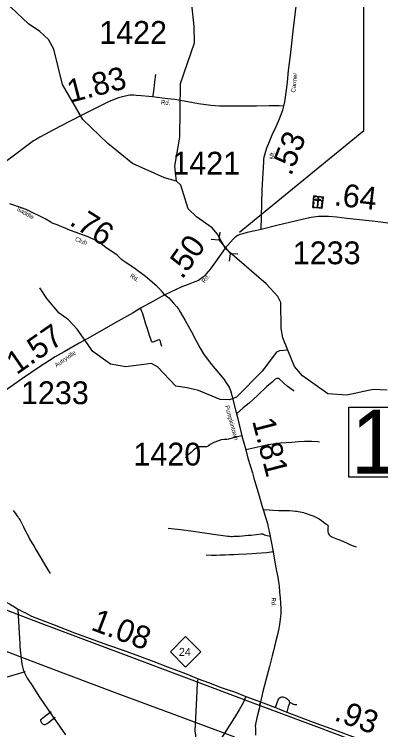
# Model space of a CAD drawing. Extents: x 2093524 to 2270757, y 289120 to 570408.
# Drawn here: x 2112932 to 2120967, y 449270 to 464958 of the extents above; entities that cross this region are included whole.
import ezdxf

# ---------------------------------------------------------------- set-up
doc = ezdxf.new("R2010")
doc.units = 0
for name, color, linetype in [('Exist Cultural Cemetery CELL', 7, 'Continuous'), ('Exist Hydrographic Creek Single Shore', 7, 'Continuous'), ('Exist Hydrographic Misc Water Feature', 7, 'Continuous'), ('Exist Railroad Mainline', 7, 'Continuous'), ('Exist Road Non-System Type 51', 7, 'Continuous'), ('Exist Road Primary NC Attributed', 7, 'Continuous'), ('Exist Road Primary NC Mileage Hundredths English Label', 7, 'Continuous'), ('Exist Road Primary NC Shield CELL', 7, 'Continuous'), ('Exist Road Primary NC Shield Number Label', 7, 'Continuous'), ('Exist Road Secondary Mileage Hundredths English Label', 7, 'Continuous'), ('Exist Road Secondary Structure Pipe CELL', 7, 'Continuous'), ('Exist Road Secondary Structure Pipe Number Label', 7, 'Continuous'), ('Exist Road Secondary Structure Standard Bridge Number Label', 7, 'Continuous'), ('Exist Road Secondary Type 51 Attributed', 7, 'Continuous'), ('Exist Road Secondary Type 51 Label', 7, 'Continuous'), ('Exist Road Secondary Type 51 Number Label', 7, 'Continuous'), ('Exist Utilities Telephone Line', 7, 'Continuous')]:
    doc.layers.add(name, color=color, linetype=linetype)

msp = doc.modelspace()

# ---------------------------------------------------------------- linework, layer by layer
at = {"layer": 'Exist Cultural Cemetery CELL'}
for points in [[(2119504, 460976), (2119702, 460956), (2119677, 460703), (2119479, 460722)], [(2119493, 460859), (2119497, 460902), (2119508, 460901), (2119504, 460858)], [(2119500, 460933), (2119511, 460932), (2119514, 460964), (2119555, 460960), (2119556, 460971), (2119504, 460976)], [(2119538, 460904), (2119536, 460885), (2119653, 460874), (2119655, 460892)], [(2119610, 460936), (2119591, 460938), (2119571, 460736), (2119590, 460734)], [(2119578, 460968), (2119629, 460963), (2119628, 460952), (2119577, 460957)], [(2119698, 460913), (2119687, 460914), (2119690, 460946), (2119650, 460950), (2119651, 460961), (2119702, 460956)], [(2119512, 460719), (2119513, 460731), (2119491, 460733), (2119495, 460773), (2119484, 460774), (2119479, 460722)], [(2119486, 460792), (2119490, 460835), (2119501, 460834), (2119497, 460791)], [(2119644, 460706), (2119645, 460717), (2119667, 460715), (2119671, 460755), (2119682, 460754), (2119677, 460703)], [(2119673, 460776), (2119677, 460819), (2119689, 460818), (2119684, 460775)], [(2119679, 460841), (2119684, 460884), (2119695, 460883), (2119691, 460840)], [(2119537, 460728), (2119622, 460720), (2119621, 460708), (2119536, 460717)]]:
    msp.add_lwpolyline(points, close=True, dxfattribs=at)
at = {"layer": 'Exist Hydrographic Creek Single Shore'}
for points in [[(2116489, 461297), (2116455, 461629), (2116560, 462264), (2116580, 463438), (2116884, 464331), (2116874, 464688), (2116822, 465172), (2117018, 465991), (2117009, 466280), (2116831, 466972), (2116679, 467346), (2116310, 467928), (2115948, 468752), (2115872, 468966), (2115510, 469813), (2115317, 470188), (2115173, 470713), (2115212, 471296), (2115343, 471854), (2115333, 472287), (2115223, 472664)], [(2116489, 461297), (2116222, 461372), (2115521, 461684), (2114986, 462125), (2114434, 462654), (2113989, 463417), (2113802, 464192), (2113685, 464408), (2113492, 464582), (2113242, 464748), (2112857, 465113), (2112396, 465726)], [(2117553, 459826), (2117386, 460135), (2117268, 460275), (2116927, 460514), (2116742, 460689), (2116581, 461214), (2116489, 461297)], [(2118931, 457591), (2118821, 457865), (2118787, 458066), (2118775, 458640), (2118708, 458773), (2118457, 459047), (2117649, 459742), (2117553, 459826)], [(2121109, 456717), (2120801, 456727), (2120226, 456607), (2119810, 456638), (2119250, 457027), (2119074, 457234), (2118931, 457591)]]:
    msp.add_lwpolyline(points, dxfattribs=at)
at = {"layer": 'Exist Hydrographic Misc Water Feature'}
msp.add_lwpolyline([(2118931, 457591), (2118748, 457575), (2118681, 457550), (2118366, 457133), (2117801, 456564), (2117652, 456504), (2117443, 456512), (2116968, 456708), (2116726, 456766), (2116475, 456807), (2116075, 457228), (2115940, 457303), (2115375, 457226), (2115041, 457285), (2114656, 457565), (2114312, 458054), (2114120, 458261), (2113919, 458403), (2113643, 458727), (2113492, 458959)], dxfattribs=at)
at = {"layer": 'Exist Railroad Mainline'}
for points in [[(2107219, 453960), (2107704, 453778), (2108825, 453368), (2109960, 452952), (2111077, 452536), (2112390, 452041), (2113015, 451799)], [(2113015, 451799), (2113513, 451606), (2115446, 450884), (2116647, 450432), (2118165, 449863), (2119561, 449338), (2120720, 448904), (2121926, 448462), (2122765, 448156), (2122833, 448131)]]:
    msp.add_lwpolyline(points, dxfattribs=at)
at = {"layer": 'Exist Road Non-System Type 51'}
msp.add_line((2118330, 449883), (2118301, 449791), dxfattribs=at)
for points in [[(2116028, 463638), (2116008, 463474), (2115989, 463328), (2115977, 463224), (2115964, 463146)], [(2116164, 457671), (2116156, 457715), (2116136, 457783), (2116135, 457793), (2116133, 457801), (2116125, 457812), (2116117, 457818), (2116111, 457817), (2116078, 457810), (2115992, 457774), (2115971, 457770), (2115954, 457768), (2115946, 457774), (2115941, 457792), (2115895, 457918), (2115850, 458062), (2115812, 458187), (2115774, 458317), (2115741, 458409), (2115729, 458443), (2115697, 458511)], [(2119067, 456694), (2119045, 456712), (2118918, 456805), (2118826, 456885), (2118747, 456956), (2118723, 456970), (2118687, 456970), (2118654, 456954), (2118584, 456892), (2118472, 456795), (2118269, 456607), (2118081, 456434), (2117952, 456325), (2117808, 456199)], [(2117922, 455717), (2117858, 455697), (2117740, 455669), (2117626, 455642), (2117594, 455632), (2117544, 455632), (2117470, 455624), (2117408, 455607), (2117308, 455571), (2117228, 455523), (2117182, 455487), (2117150, 455476), (2117084, 455472), (2116972, 455470), (2116923, 455446), (2116867, 455409), (2116813, 455351), (2116735, 455289), (2116707, 455261), (2116699, 455245), (2116683, 455222)], [(2119621, 455576), (2119589, 455580), (2119457, 455589), (2119297, 455588), (2119167, 455582), (2119017, 455571), (2118773, 455550), (2118497, 455519), (2118337, 455483), (2118011, 455404)], [(2113724, 452693), (2113667, 452789), (2113582, 452935), (2113507, 453060), (2113443, 453171), (2113398, 453245), (2113352, 453325), (2113323, 453369), (2113303, 453403), (2113285, 453428), (2113265, 453460), (2113247, 453498), (2113218, 453554), (2113194, 453608), (2113165, 453661), (2113143, 453709), (2113121, 453757), (2113099, 453799), (2113076, 453841), (2113058, 453871), (2113046, 453891), (2113027, 453919), (2113008, 453946), (2112985, 453978), (2112965, 454010), (2112939, 454048), (2112917, 454078)], [(2118389, 454098), (2118519, 454090), (2118599, 454087), (2118723, 454080), (2118845, 454077), (2118968, 454077), (2119040, 454071), (2119101, 454064), (2119127, 454060), (2119160, 454055), (2119199, 454047), (2119237, 454040), (2119274, 454031), (2119307, 454021), (2119343, 454010), (2119414, 453984), (2119484, 453959), (2119526, 453939), (2119572, 453917), (2119614, 453894), (2119666, 453856), (2119707, 453828), (2119745, 453801), (2119777, 453779), (2119796, 453765), (2119805, 453758), (2119811, 453743), (2119813, 453729), (2119811, 453695), (2119810, 453635), (2119811, 453608), (2119816, 453583), (2119824, 453563), (2119835, 453546), (2119849, 453531), (2119867, 453517), (2119883, 453508), (2119911, 453494), (2119943, 453480), (2120021, 453450), (2120087, 453427), (2120169, 453392), (2120233, 453362), (2120307, 453327), (2120364, 453305), (2120429, 453281)], [(2118543, 453509), (2118447, 453530), (2118421, 453538), (2118399, 453548), (2118381, 453556), (2118369, 453558), (2118361, 453558), (2118349, 453558), (2118233, 453545), (2118127, 453532), (2118061, 453526), (2117994, 453521), (2117933, 453516), (2117866, 453510), (2117810, 453506), (2117774, 453504), (2117744, 453504), (2117717, 453503), (2117688, 453503), (2117654, 453505), (2117614, 453509), (2117564, 453516), (2117348, 453543), (2117106, 453577), (2116806, 453627), (2116579, 453650), (2116371, 453677), (2116306, 453684)], [(2118605, 453170), (2118472, 453149), (2118354, 453140), (2118242, 453133), (2118150, 453127), (2118026, 453120), (2117848, 453113), (2117739, 453108), (2117653, 453105), (2117553, 453101), (2117449, 453096), (2117367, 453093), (2117301, 453089), (2117257, 453088), (2117142, 453097)], [(2113169, 450537), (2112743, 450414), (2112397, 450312), (2112300, 450290), (2112255, 450279), (2112183, 450254), (2112102, 450226), (2112054, 450207), (2112046, 450203), (2112026, 450198), (2111988, 450196), (2111916, 450192), (2111828, 450190), (2111805, 450188), (2111771, 450187), (2111717, 450182), (2111623, 450166)], [(2116922, 449040), (2116909, 449147), (2116896, 449247), (2116913, 449527), (2116935, 449959), (2116949, 450289), (2116966, 450389)], [(2118009, 450000), (2117954, 449857), (2117864, 449708), (2117761, 449537), (2117610, 449298), (2117545, 449203), (2117410, 448992), (2117362, 448904), (2117339, 448847)], [(2118661, 449754), (2118688, 449844), (2118704, 449884), (2118720, 449922), (2118731, 449948), (2118743, 449964), (2118759, 449978), (2118779, 449986), (2118797, 449991), (2118817, 449991), (2118841, 449985), (2118863, 449975), (2118891, 449961), (2118913, 449945), (2118933, 449931), (2118947, 449920), (2118957, 449903), (2118962, 449889)], [(2118330, 449883), (2118305, 449730), (2118251, 449532), (2118218, 449394), (2118215, 449343), (2118218, 449310), (2118222, 449217), (2118222, 449149)], [(2118962, 449889), (2118966, 449856), (2118960, 449828), (2118940, 449769), (2118910, 449657)], [(2118962, 449889), (2118996, 449862), (2119016, 449849), (2119034, 449839), (2119058, 449830), (2119080, 449826), (2119098, 449825), (2119126, 449825)], [(2113826, 449536), (2113671, 449412), (2113653, 449398), (2113634, 449388), (2113618, 449382), (2113601, 449377), (2113584, 449378), (2113569, 449383), (2113558, 449392), (2113546, 449405), (2113537, 449415), (2113529, 449427), (2113522, 449440), (2113515, 449455), (2113512, 449467), (2113513, 449481), (2113516, 449492), (2113525, 449503), (2113536, 449515), (2113554, 449533), (2113594, 449563), (2113738, 449669)]]:
    msp.add_lwpolyline(points, dxfattribs=at)
at = {"layer": 'Exist Road Primary NC Attributed'}
for points in [[(2108369, 453970), (2108678, 453841), (2108992, 453716), (2109651, 453469), (2109957, 453357), (2110420, 453180), (2110927, 452990), (2111158, 452895), (2111300, 452839), (2111481, 452761), (2111679, 452677), (2111876, 452577), (2111992, 452513), (2112719, 452091), (2112846, 452016), (2112934, 451961), (2113011, 451916)], [(2113011, 451916), (2113059, 451889), (2113109, 451863), (2113176, 451830), (2113312, 451761), (2113461, 451703), (2113769, 451585), (2114254, 451396), (2115001, 451124), (2115317, 451017), (2115676, 450881), (2115992, 450764), (2116293, 450651), (2116684, 450499), (2116966, 450389), (2117194, 450303), (2117467, 450198), (2117601, 450153), (2117760, 450099), (2117886, 450052), (2118009, 450000), (2118113, 449965), (2118330, 449883)], [(2118330, 449883), (2118661, 449754), (2118910, 449657), (2119484, 449439), (2119950, 449264), (2120430, 449092), (2120558, 449049), (2120718, 448994), (2120871, 448938), (2121055, 448870), (2121206, 448816), (2121382, 448751), (2121570, 448681), (2121778, 448608), (2122085, 448495), (2122254, 448410), (2122440, 448345), (2122678, 448257), (2122919, 448177)]]:
    msp.add_lwpolyline(points, dxfattribs=at)
at = {"layer": 'Exist Road Primary NC Shield CELL'}
msp.add_lwpolyline([(2116355, 450978), (2116688, 451311), (2117021, 450978), (2116688, 450645)], close=True, dxfattribs=at)
at = {"layer": 'Exist Road Secondary Structure Pipe CELL'}
for p, q in [((2117438, 460179), (2117417, 460014)), ((2117251, 460025), (2117417, 460014)), ((2117417, 460014), (2117670, 459708)), ((2117649, 459543), (2117670, 459708)), ((2117836, 459697), (2117670, 459708))]:
    msp.add_line(p, q, dxfattribs=at)
at = {"layer": 'Exist Road Secondary Structure Pipe Number Label'}
msp.add_lwpolyline([(2117868, 460183), (2120600, 462409), (2120600, 465976)], dxfattribs=at)
at = {"layer": 'Exist Road Secondary Structure Standard Bridge Number Label'}
msp.add_lwpolyline([(2120265, 456342), (2123981, 456342), (2123981, 454806), (2120265, 454806)], close=True, dxfattribs=at)
at = {"layer": 'Exist Road Secondary Type 51 Attributed'}
for points in [[(2118839, 462945), (2118861, 463041), (2118879, 463139), (2118892, 463241), (2118920, 463471), (2118947, 463727), (2118987, 464057), (2119049, 464589), (2119133, 465328), (2119170, 465620), (2119185, 465724), (2119193, 465758), (2119207, 465808), (2119217, 465848), (2119258, 465944), (2119350, 466149), (2119443, 466359), (2119586, 466677), (2119701, 466924), (2119753, 467026)], [(2118839, 462945), (2118741, 462952), (2118521, 462951), (2118245, 462947), (2117971, 462945), (2117747, 462943), (2117575, 462942), (2117435, 462947), (2117245, 462961), (2116973, 462998), (2116734, 463039), (2116450, 463092), (2116290, 463107), (2115964, 463146), (2115882, 463152), (2115711, 463171), (2115605, 463180), (2115551, 463184), (2115465, 463182), (2115364, 463166), (2115219, 463129), (2115012, 463048), (2114822, 462950), (2114413, 462744), (2113943, 462502), (2113488, 462263), (2113394, 462208), (2113352, 462182), (2113293, 462138), (2113175, 462049), (2112965, 461893), (2112712, 461702)], [(2118345, 460241), (2118368, 461099), (2118379, 461357), (2118394, 461599), (2118402, 461721), (2118406, 461769), (2118413, 461831), (2118425, 461879), (2118447, 461959), (2118471, 462031), (2118510, 462130), (2118590, 462316), (2118671, 462494), (2118746, 462668), (2118794, 462784), (2118818, 462855), (2118839, 462945)], [(2116231, 458805), (2116178, 458865), (2116123, 458927), (2116059, 458994), (2115806, 459209), (2115579, 459378), (2115357, 459530), (2115293, 459577), (2115240, 459623), (2115190, 459673), (2115136, 459713), (2114948, 459840), (2114835, 459922), (2114721, 459995), (2114549, 460075), (2114164, 460219), (2113875, 460342), (2113807, 460364), (2113745, 460385), (2113730, 460401), (2113609, 460472), (2113219, 460661), (2113191, 460677), (2113093, 460715), (2112832, 460805)], [(2121695, 460317), (2121577, 460329), (2121326, 460359), (2121122, 460380), (2120972, 460398), (2120777, 460422), (2120639, 460438), (2120435, 460459), (2120224, 460483), (2120008, 460508), (2119819, 460527), (2119717, 460527), (2119605, 460523), (2119442, 460503), (2119272, 460462), (2119089, 460419), (2118720, 460335), (2118345, 460241)], [(2118345, 460241), (2118217, 460212), (2118039, 460170), (2117943, 460147), (2117913, 460138), (2117879, 460127), (2117833, 460104), (2117798, 460083), (2117762, 460056), (2117728, 460025), (2117553, 459826)], [(2117553, 459826), (2117342, 459527), (2117228, 459369), (2117190, 459325), (2117142, 459268), (2117114, 459234), (2117083, 459204), (2117032, 459161), (2116969, 459122), (2116890, 459089), (2116741, 459035), (2116603, 458982), (2116231, 458805)], [(2116231, 458805), (2116136, 458757), (2115986, 458670), (2115697, 458511), (2115539, 458414), (2115212, 458227), (2115040, 458134), (2114848, 458022), (2114529, 457842), (2114357, 457746), (2114026, 457555), (2113830, 457444), (2113475, 457223), (2113111, 456971), (2112716, 456696)], [(2116231, 458805), (2116324, 458739), (2116425, 458624), (2116493, 458546), (2116537, 458484), (2116579, 458418), (2116676, 458247), (2116807, 458011), (2116922, 457796), (2117006, 457640), (2117083, 457516), (2117139, 457432), (2117254, 457279), (2117419, 457085), (2117481, 457010), (2117531, 456946), (2117581, 456878), (2117616, 456822), (2117642, 456778), (2117670, 456712), (2117703, 456597), (2117808, 456199), (2117826, 456113), (2117922, 455717), (2118011, 455404), (2118056, 455228), (2118155, 454903), (2118188, 454783), (2118227, 454642), (2118300, 454398), (2118362, 454187), (2118389, 454098), (2118441, 453931), (2118482, 453790), (2118500, 453713), (2118514, 453654), (2118524, 453611), (2118534, 453558), (2118543, 453509), (2118573, 453362), (2118595, 453247), (2118605, 453170), (2118647, 452943), (2118685, 452745), (2118709, 452617), (2118724, 452516), (2118737, 452426), (2118750, 452286), (2118763, 452162), (2118773, 452046), (2118776, 451933), (2118775, 451811), (2118764, 451696), (2118750, 451574), (2118735, 451493), (2118721, 451424), (2118698, 451328), (2118669, 451216), (2118639, 451095), (2118614, 450997), (2118587, 450887), (2118564, 450799), (2118526, 450653), (2118480, 450467), (2118414, 450220), (2118384, 450107), (2118359, 450005), (2118330, 449883)], [(2113011, 451916), (2113021, 451645), (2113043, 451269), (2113051, 451169), (2113056, 451086), (2113069, 450955), (2113078, 450897), (2113097, 450704), (2113125, 450590), (2113149, 450531), (2113215, 450402), (2113321, 450243), (2113487, 449982), (2113756, 449590), (2114051, 449155)]]:
    msp.add_lwpolyline(points, dxfattribs=at)
at = {"layer": 'Exist Utilities Telephone Line'}
msp.add_lwpolyline([(2105807, 453400), (2106839, 453144), (2107342, 453027), (2109094, 452364), (2110400, 451877), (2111697, 451383), (2112393, 451121), (2113608, 450660), (2115178, 450072), (2116384, 449622), (2117759, 449111)], dxfattribs=at)

# ---------------------------------------------------------------- texts
at = {"layer": 'Exist Road Primary NC Mileage Hundredths English Label'}
for s, rotation, p in [('1.08', 339.2343, (2114589, 451469)), ('.93', 339.8056, (2119925, 449486))]:
    msp.add_text(s, height=500, rotation=rotation, dxfattribs=at).set_placement(p)
at = {"layer": 'Exist Road Primary NC Shield Number Label'}
msp.add_text('24', height=175, dxfattribs=at).set_placement((2116542, 450889))
at = {"layer": 'Exist Road Secondary Mileage Hundredths English Label'}
for s, rotation, p in [('1.83', 14.4142, (2114165, 463018)), ('.53', 68.9537, (2119002, 461396)), ('.64', 353.5441, (2119929, 460769)), ('.76', 327.4768, (2114117, 460356)), ('.50', 54.8443, (2116614, 459128)), ('1.57', 34.8302, (2112981, 457042)), ('1.81', 284.4409, (2118145, 456043))]:
    msp.add_text(s, height=500, rotation=rotation, dxfattribs=at).set_placement(p)
at = {"layer": 'Exist Road Secondary Structure Standard Bridge Number Label'}
msp.add_text('101', height=1400, dxfattribs=at).set_placement((2120315, 454885))
at = {"layer": 'Exist Road Secondary Type 51 Label'}
for s, rotation, p in [('Carmel', 83.2217, (2119092, 463238)), ('Rd.', 353.2195, (2116144, 462988)), ('Mt.', 84.1893, (2118619, 461778)), ('Saddle', 329.3288, (2112976, 460665)), ('Club', 339.5728, (2114255, 459992)), ('Rd.', 325.3764, (2115459, 459203)), ('Rd.', 54.0177, (2117106, 459053)), ('Autryville', 34.7071, (2113857, 457213)), ('Pumpkintown', 285.5489, (2117548, 456368)), ('Rd.', 270.2079, (2118574, 452170))]:
    msp.add_text(s, height=95, rotation=rotation, dxfattribs=at).set_placement(p)
at = {"layer": 'Exist Road Secondary Type 51 Number Label'}
for s, p in [('1422', (2114793, 464310)), ('1421', (2116397, 461443)), ('1233', (2119038, 459477)), ('1233', (2113078, 456409)), ('1420', (2115544, 455063))]:
    msp.add_text(s, height=500, dxfattribs=at).set_placement(p)

doc.saveas('drawing.dxf')
